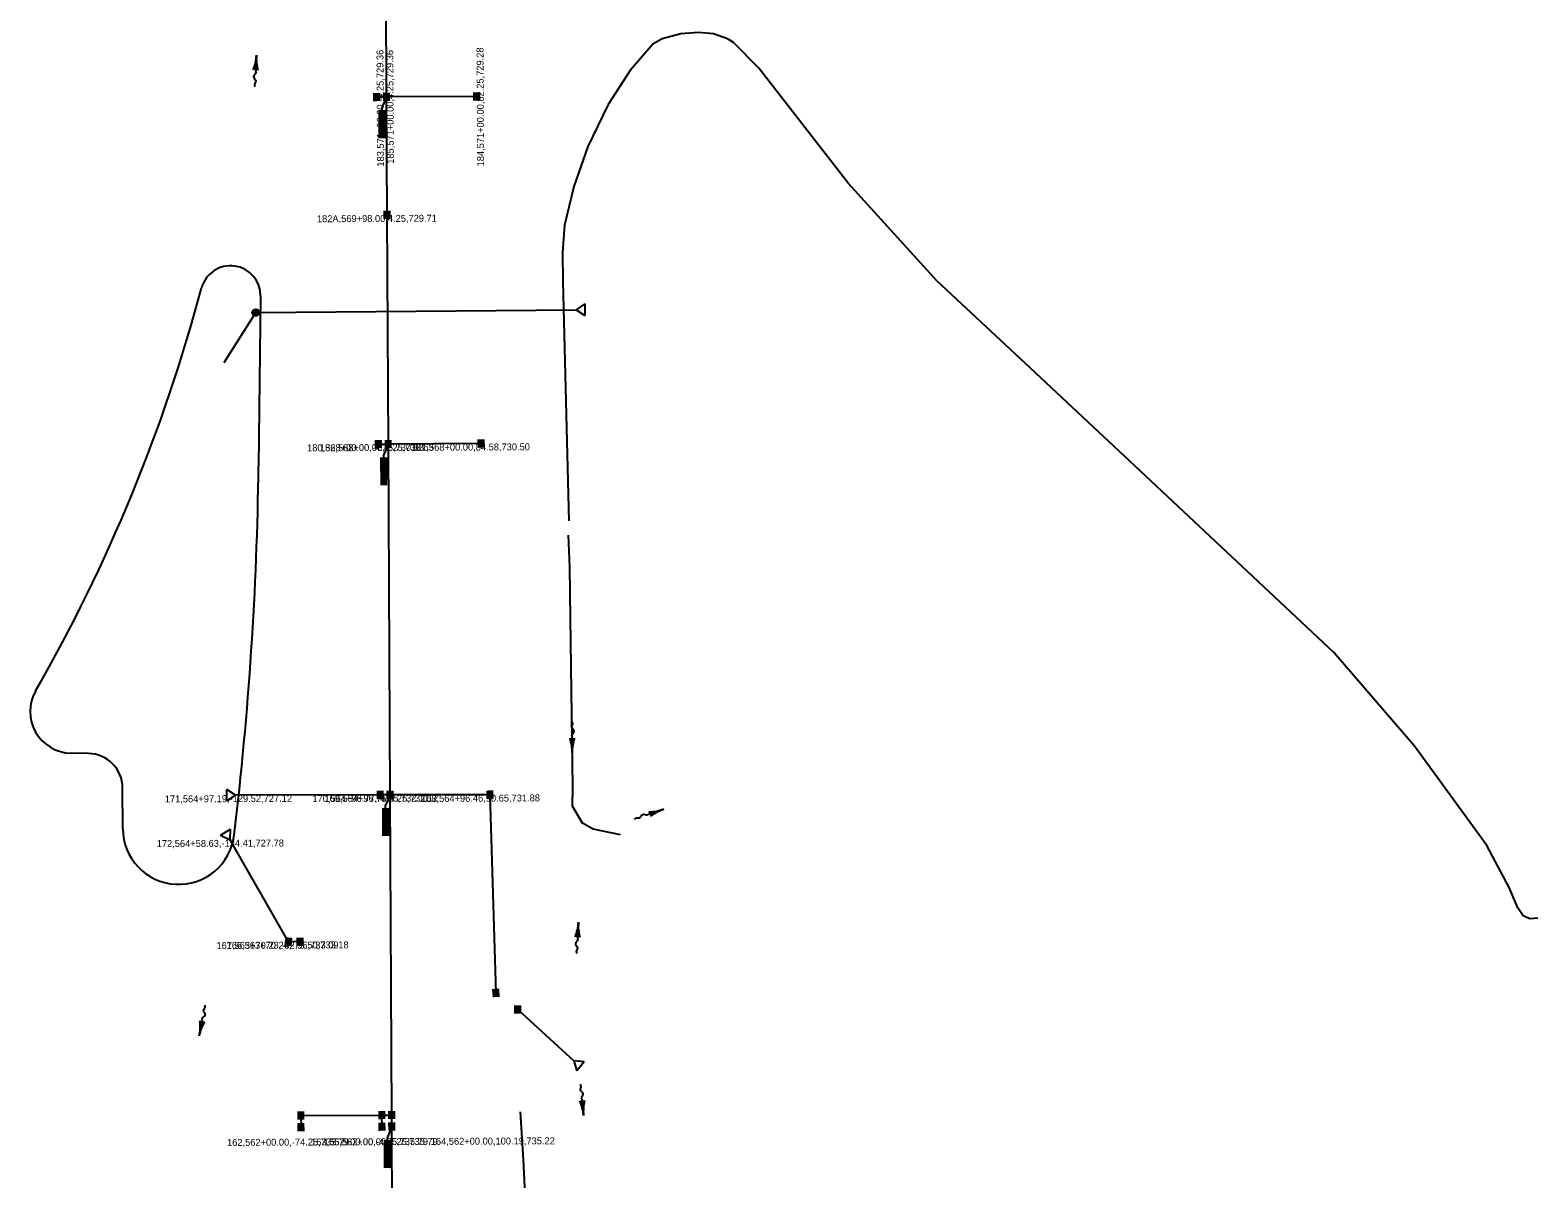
# Model space of a CAD drawing. Extents: x 593481 to 595602, y 151646 to 157396.
# Drawn here: x 594042 to 595346, y 155440 to 156433 of the extents above; entities that cross this region are included whole.
import ezdxf

# ---------------------------------------------------------------- set-up
doc = ezdxf.new("R2010")
doc.units = 0
for name, color, linetype in [('P_ALI_50_Equation', 7, 'Continuous'), ('P_DRN_Flow', 7, 'Continuous'), ('P_DRN_Inlet', 7, 'Continuous'), ('P_DRN_Pond', 7, 'Continuous'), ('P_DRN_SS', 7, 'Continuous'), ('P_DRN_SS_MH', 7, 'Continuous'), ('P_DRN_SS_UG', 7, 'Continuous')]:
    doc.layers.add(name, color=color, linetype=linetype)

msp = doc.modelspace()

# ---------------------------------------------------------------- linework, layer by layer
at = {"layer": 'P_DRN_Flow'}
for p, q in [((594238, 156411.3), (594237.2, 156397.2)), ((594510.9, 155808.1), (594511, 155822.3)), ((594590.1, 155759.5), (594576.7, 155755)), ((594516.3, 155661.9), (594515.5, 155647.8)), ((594188.6, 155563.7), (594191.3, 155577.6)), ((594520.8, 155494.8), (594519.5, 155508.9))]:
    msp.add_line(p, q, dxfattribs=at)
for points in [[(594239.3, 156398.4), (594237.5, 156401.7), (594235.3, 156398.6)], [(594509, 155820.9), (594511, 155817.7), (594513, 155820.9)], [(594578.6, 155753.5), (594581, 155756.5), (594577.3, 155757.3)], [(594517.6, 155649), (594515.7, 155652.3), (594513.6, 155649.2)], [(594189.1, 155576.7), (594190.4, 155573.2), (594193, 155575.9)], [(594517.6, 155507.4), (594519.9, 155504.4), (594521.6, 155507.8)]]:
    msp.add_lwpolyline(points, dxfattribs=at)
for centre, start, end in [((594196.1, 156413.6), 339.0322, 356.7946), ((594279.9, 156408.9), 176.7946, 194.5569), ((594469, 155808.4), 359.6117, 17.374), ((594552.9, 155807.9), 161.8494, 179.6117), ((594576.8, 155799.3), 270.74, 288.5023), ((594603.4, 155719.7), 108.5023, 126.2646), ((594474.4, 155664.2), 339.0322, 356.7946), ((594558.2, 155659.5), 176.7946, 194.5569), ((594147.4, 155571.7), 349.0067, 6.769), ((594229.8, 155555.7), 151.2443, 169.0067), ((594479, 155490.9), 5.4126, 23.1749), ((594562.6, 155498.8), 167.6503, 185.4126)]:
    msp.add_arc(centre, 42, start, end, dxfattribs=at)
for points in [[(594237.2, 156397.2), (594237.5, 156396.4), (594235.4, 156392.9), (594237.4, 156388.8), (594236.3, 156386), (594236.8, 156384.3)], [(594511, 155822.3), (594510.7, 155823.1), (594512.6, 155826.7), (594510.5, 155830.6), (594511.4, 155833.4), (594510.8, 155835.1)], [(594576.7, 155755), (594576, 155754.5), (594572, 155755.1), (594569, 155751.8), (594566, 155751.8), (594564.6, 155750.6)], [(594515.5, 155647.8), (594515.8, 155647), (594513.7, 155643.5), (594515.6, 155639.4), (594514.5, 155636.7), (594515.1, 155634.9)], [(594191.3, 155577.6), (594191.1, 155578.4), (594193.7, 155581.6), (594192.3, 155585.9), (594193.7, 155588.5), (594193.4, 155590.3)], [(594519.5, 155508.9), (594519.1, 155509.6), (594520.6, 155513.4), (594518.1, 155517.1), (594518.7, 155520), (594517.9, 155521.7)]]:
    msp.add_spline(points, degree=3, dxfattribs=at)
at = {"layer": 'P_DRN_Inlet'}
for p, q in [((594339.8, 156371.7), (594339.8, 156378.6)), ((594340.7, 156371.7), (594340.7, 156378.6)), ((594341.6, 156371.7), (594341.6, 156378.6)), ((594342.5, 156371.8), (594342.5, 156378.6)), ((594343.4, 156371.8), (594343.4, 156378.6)), ((594344.3, 156371.8), (594344.3, 156378.6)), ((594348.3, 156371.8), (594348.3, 156378.7)), ((594349.2, 156371.8), (594349.2, 156378.7)), ((594350.1, 156371.8), (594350.1, 156378.7)), ((594351, 156371.8), (594351, 156378.7)), ((594351.9, 156371.8), (594351.9, 156378.7)), ((594352.8, 156371.8), (594352.8, 156378.7)), ((594426.3, 156372.2), (594426.3, 156379.1)), ((594427.2, 156372.2), (594427.2, 156379.1)), ((594428.1, 156372.2), (594428.1, 156379.1)), ((594429, 156372.2), (594429, 156379.1)), ((594429.9, 156372.2), (594429.9, 156379.1)), ((594430.8, 156372.2), (594430.8, 156379.1)), ((594344.1, 156363.7), (594344.2, 156339.7)), ((594345, 156363.7), (594345.1, 156339.7)), ((594345.9, 156363.7), (594346, 156339.7)), ((594346.8, 156363.7), (594346.9, 156339.7)), ((594347.7, 156363.7), (594347.8, 156339.7)), ((594348.6, 156363.7), (594348.7, 156339.7)), ((594348.8, 156269.8), (594348.8, 156276.7)), ((594349.7, 156269.8), (594349.7, 156276.7)), ((594350.6, 156269.8), (594350.6, 156276.7)), ((594351.5, 156269.8), (594351.5, 156276.7)), ((594352.4, 156269.8), (594352.4, 156276.7)), ((594353.3, 156269.8), (594353.3, 156276.7)), ((594341.3, 156071.7), (594341.3, 156078.6)), ((594342.2, 156071.7), (594342.2, 156078.6)), ((594343.1, 156071.8), (594343.1, 156078.6)), ((594344, 156071.8), (594344, 156078.6)), ((594344.9, 156071.8), (594344.9, 156078.6)), ((594345.8, 156071.8), (594345.8, 156078.6)), ((594349.8, 156071.8), (594349.8, 156078.7)), ((594350.7, 156071.8), (594350.7, 156078.7)), ((594351.6, 156071.8), (594351.6, 156078.7)), ((594352.5, 156071.8), (594352.5, 156078.7)), ((594353.4, 156071.8), (594353.4, 156078.7)), ((594354.3, 156071.8), (594354.3, 156078.7)), ((594430.2, 156072.2), (594430.1, 156079)), ((594431.1, 156072.2), (594431, 156079)), ((594432, 156072.2), (594431.9, 156079.1)), ((594432.9, 156072.2), (594432.8, 156079.1)), ((594433.8, 156072.2), (594433.7, 156079.1)), ((594434.7, 156072.3), (594434.6, 156079.1)), ((594345.6, 156063.7), (594345.7, 156039.7)), ((594346.5, 156063.7), (594346.6, 156039.7)), ((594347.4, 156063.7), (594347.5, 156039.7)), ((594348.3, 156063.7), (594348.4, 156039.7)), ((594349.2, 156063.7), (594349.3, 156039.7)), ((594350.1, 156063.7), (594350.2, 156039.7)), ((594342.9, 155768.5), (594342.9, 155775.4)), ((594343.8, 155768.5), (594343.8, 155775.4)), ((594344.7, 155768.5), (594344.7, 155775.4)), ((594345.6, 155768.5), (594345.6, 155775.4)), ((594346.5, 155768.5), (594346.5, 155775.4)), ((594347.4, 155768.5), (594347.4, 155775.4)), ((594351.4, 155768.5), (594351.4, 155775.4)), ((594352.3, 155768.5), (594352.3, 155775.4)), ((594353.2, 155768.5), (594353.2, 155775.4)), ((594354.1, 155768.5), (594354.1, 155775.4)), ((594355, 155768.6), (594355, 155775.4)), ((594355.9, 155768.6), (594355.9, 155775.4)), ((594437.9, 155768.6), (594437.7, 155775.5)), ((594438.8, 155768.7), (594438.6, 155775.5)), ((594439.7, 155768.7), (594439.5, 155775.6)), ((594440.6, 155768.7), (594440.4, 155775.6)), ((594441.5, 155768.7), (594441.3, 155775.6)), ((594442.4, 155768.8), (594442.2, 155775.6)), ((594347.2, 155760.5), (594347.3, 155736.5)), ((594348.1, 155760.5), (594348.2, 155736.5)), ((594349, 155760.5), (594349.1, 155736.5)), ((594349.9, 155760.5), (594350, 155736.5)), ((594350.8, 155760.5), (594350.9, 155736.5)), ((594351.7, 155760.5), (594351.8, 155736.5)), ((594263.2, 155641.8), (594263.9, 155648.7)), ((594264.1, 155641.7), (594264.8, 155648.6)), ((594265, 155641.7), (594265.7, 155648.5)), ((594265.9, 155641.6), (594266.6, 155648.4)), ((594266.8, 155641.5), (594267.5, 155648.3)), ((594267.7, 155641.4), (594268.4, 155648.2)), ((594273.5, 155641.6), (594273.5, 155648.5)), ((594274.4, 155641.6), (594274.4, 155648.5)), ((594275.3, 155641.6), (594275.3, 155648.5)), ((594276.2, 155641.6), (594276.2, 155648.5)), ((594277.1, 155641.6), (594277.1, 155648.5)), ((594278, 155641.7), (594278, 155648.5)), ((594443.1, 155597.2), (594442.7, 155604.1)), ((594444, 155597.3), (594443.6, 155604.1)), ((594444.9, 155597.3), (594444.5, 155604.2)), ((594445.8, 155597.4), (594445.4, 155604.2)), ((594446.7, 155597.4), (594446.3, 155604.3)), ((594447.6, 155597.5), (594447.2, 155604.3)), ((594461.8, 155582.9), (594461.8, 155589.8)), ((594462.7, 155582.9), (594462.7, 155589.8)), ((594463.6, 155582.9), (594463.6, 155589.8)), ((594464.5, 155583), (594464.5, 155589.8)), ((594465.4, 155583), (594465.4, 155589.8)), ((594466.3, 155583), (594466.3, 155589.8)), ((594274.3, 155491.4), (594274.3, 155498.3)), ((594275.2, 155491.4), (594275.2, 155498.3)), ((594276.1, 155491.4), (594276.1, 155498.3)), ((594277, 155491.4), (594277, 155498.3)), ((594277.9, 155491.4), (594277.9, 155498.3)), ((594278.8, 155491.4), (594278.8, 155498.3)), ((594344.3, 155491.7), (594344.3, 155498.6)), ((594345.2, 155491.8), (594345.2, 155498.6)), ((594346.1, 155491.8), (594346.1, 155498.6)), ((594347, 155491.8), (594347, 155498.6)), ((594347.9, 155491.8), (594347.9, 155498.6)), ((594348.8, 155491.8), (594348.8, 155498.6)), ((594352.8, 155491.8), (594352.8, 155498.7)), ((594353.7, 155491.8), (594353.7, 155498.7)), ((594354.6, 155491.8), (594354.6, 155498.7)), ((594355.5, 155491.8), (594355.5, 155498.7)), ((594356.4, 155491.8), (594356.4, 155498.7)), ((594357.3, 155491.8), (594357.3, 155498.7)), ((594274.4, 155481.4), (594274.3, 155488.3)), ((594275.3, 155481.4), (594275.2, 155488.3)), ((594276.2, 155481.4), (594276.1, 155488.3)), ((594277.1, 155481.4), (594277, 155488.3)), ((594278, 155481.4), (594277.9, 155488.3)), ((594278.9, 155481.4), (594278.8, 155488.3)), ((594344.4, 155481.7), (594344.3, 155488.6)), ((594345.3, 155481.8), (594345.2, 155488.6)), ((594346.2, 155481.8), (594346.1, 155488.6)), ((594347.1, 155481.8), (594347, 155488.6)), ((594348, 155481.8), (594347.9, 155488.6)), ((594348.9, 155481.8), (594348.8, 155488.6)), ((594352.9, 155481.8), (594352.8, 155488.7)), ((594353.8, 155481.8), (594353.7, 155488.7)), ((594354.7, 155481.8), (594354.6, 155488.7)), ((594355.6, 155481.8), (594355.5, 155488.7)), ((594356.5, 155481.8), (594356.4, 155488.7)), ((594357.4, 155481.8), (594357.3, 155488.7)), ((594348.6, 155473.5), (594348.8, 155449.5)), ((594349.5, 155473.5), (594349.7, 155449.5)), ((594350.4, 155473.6), (594350.6, 155449.6)), ((594351.3, 155473.6), (594351.5, 155449.6)), ((594352.2, 155473.6), (594352.4, 155449.6)), ((594353.1, 155473.6), (594353.3, 155449.6))]:
    msp.add_line(p, q, dxfattribs=at)
for points in [[(594343, 156374.2), (594343, 156376.2), (594341, 156376.2), (594341, 156374.2)], [(594351.5, 156374.2), (594351.5, 156376.2), (594349.5, 156376.2), (594349.5, 156374.2)], [(594429.5, 156374.6), (594429.5, 156376.6), (594427.5, 156376.6), (594427.5, 156374.6)], [(594345.3, 156359), (594345.4, 156344.4), (594347.4, 156344.4), (594347.3, 156359)], [(594352.1, 156272.2), (594352, 156274.2), (594350, 156274.2), (594350.1, 156272.2)], [(594344.6, 156074.2), (594344.6, 156076.2), (594342.6, 156076.2), (594342.6, 156074.2)], [(594353.1, 156074.2), (594353.1, 156076.2), (594351.1, 156076.2), (594351.1, 156074.2)], [(594433.4, 156074.7), (594433.4, 156076.7), (594431.4, 156076.6), (594431.4, 156074.6)], [(594346.9, 156058.9), (594347, 156044.4), (594349, 156044.4), (594348.9, 156058.9)], [(594346.1, 155771), (594346.1, 155773), (594344.1, 155773), (594344.1, 155771)], [(594354.6, 155771), (594354.6, 155773), (594352.6, 155773), (594352.6, 155771)], [(594441, 155771.2), (594441, 155773.2), (594439, 155773.1), (594439.1, 155771.1)], [(594348.4, 155755.8), (594348.5, 155741.2), (594350.5, 155741.2), (594350.4, 155755.8)], [(594266.7, 155643.9), (594266.9, 155645.9), (594264.9, 155646.1), (594264.7, 155644.1)], [(594276.8, 155644.1), (594276.8, 155646.1), (594274.8, 155646.1), (594274.8, 155644.1)], [(594446.2, 155599.8), (594446.1, 155601.8), (594444.1, 155601.7), (594444.2, 155599.7)], [(594465.1, 155585.4), (594465, 155587.4), (594463, 155587.4), (594463.1, 155585.4)], [(594347.5, 155494.2), (594347.5, 155496.2), (594345.5, 155496.2), (594345.5, 155494.2)], [(594356, 155494.2), (594356, 155496.2), (594354, 155496.2), (594354, 155494.2)], [(594277.5, 155493.8), (594277.5, 155495.8), (594275.5, 155495.8), (594275.5, 155493.8)], [(594277.6, 155483.8), (594277.6, 155485.8), (594275.6, 155485.8), (594275.6, 155483.8)], [(594347.6, 155484.2), (594347.6, 155486.2), (594345.6, 155486.2), (594345.6, 155484.2)], [(594356.1, 155484.3), (594356.1, 155486.3), (594354.1, 155486.2), (594354.1, 155484.2)], [(594349.9, 155468.8), (594350, 155454.3), (594352, 155454.3), (594351.9, 155468.8)]]:
    msp.add_lwpolyline(points, close=True, dxfattribs=at)
at = {"layer": 'P_DRN_Pond'}
for p, q in [((594241.6, 156203), (594239.8, 156056.5)), ((594092.9, 155807.7), (594077.7, 155808)), ((594122.5, 155742.7), (594122.3, 155777.9))]:
    msp.add_line(p, q, dxfattribs=at)
for centre, radius, start, end in [((594215.6, 156203.3), 26, 359.2941, 165.091), ((592792.2, 156582.3), 1447, 330.142, 345.091), ((591269.1, 156093.1), 2971, 353.1195, 359.2941), ((594078.4, 155844), 36, 150.142, 268.9825), ((594092.3, 155777.7), 30, 0.2941, 88.9825), ((594170.8, 155742.9), 48.3, 180.2941, 353.1195)]:
    msp.add_arc(centre, radius, start, end, dxfattribs=at)
at = {"layer": 'P_DRN_SS'}
for p, q in [((594521.9, 156196.4), (594514.4, 156191.3)), ((594514.4, 156191.3), (594521.9, 156186.4)), ((594521.9, 156196.4), (594521.9, 156186.4)), ((594219.8, 155771.7), (594212.3, 155776.7)), ((594212.4, 155766.7), (594212.3, 155776.7)), ((594212.4, 155766.7), (594219.8, 155771.7)), ((594207, 155737.1), (594215.7, 155742.2)), ((594207, 155737.1), (594215.2, 155733.2)), ((594215.2, 155733.2), (594215.7, 155742.2)), ((594521.3, 155541.2), (594512.3, 155542.2)), ((594512.3, 155542.2), (594514.9, 155533.5)), ((594521.3, 155541.2), (594514.9, 155533.5))]:
    msp.add_line(p, q, dxfattribs=at)
at = {"layer": 'P_DRN_SS_MH'}
for radius in [2.98, 2.4, 1.8, 1.2, 0.6]:
    msp.add_circle((594237.4, 156188.9), radius, dxfattribs=at)
at = {"layer": 'P_DRN_SS_UG'}
for p, q in [((594350.5, 156375.2), (594349.1, 156655.2)), ((594342, 156375.2), (594350.5, 156375.2)), ((594428.5, 156375.6), (594350.5, 156375.2)), ((594351, 156273.2), (594350.5, 156375.2)), ((594352.1, 156075.2), (594351, 156273.2)), ((594210.2, 156145.7), (594237.4, 156188.9)), ((594237.4, 156188.9), (594514.4, 156191.3)), ((594343.6, 156075.2), (594352.1, 156075.2)), ((594432.4, 156075.6), (594352.1, 156075.2)), ((594353.6, 155772), (594352.1, 156075.2)), ((594345.1, 155772), (594219.8, 155771.7)), ((594353.6, 155772), (594345.1, 155772)), ((594440, 155772.1), (594353.6, 155772)), ((594355, 155495.2), (594353.6, 155772)), ((594445.2, 155600.8), (594440, 155772.1)), ((594265.8, 155645), (594215.2, 155733.2)), ((594275.8, 155645.1), (594265.8, 155645)), ((594464.1, 155586.4), (594512.3, 155542.2)), ((594276.5, 155494.8), (594346.5, 155495.2)), ((594276.5, 155494.8), (594276.6, 155484.8)), ((594346.5, 155495.2), (594355, 155495.2)), ((594346.6, 155485.2), (594346.5, 155495.2)), ((594355.1, 155485.3), (594355, 155495.2)), ((594355.9, 155330.2), (594355.1, 155485.3))]:
    msp.add_line(p, q, dxfattribs=at)
for points in [[(595345.8, 155665.5), (595338.9, 155664.9), (595333.1, 155667.3), (595328.4, 155674.3), (595321, 155691.9), (595301.8, 155728.2), (595239.2, 155814.2), (595169.4, 155895), (594997.8, 156056.2), (594907.2, 156140.8), (594826.3, 156216.4), (594749.6, 156300.6), (594672.2, 156400.2), (594650.5, 156422.2), (594645.2, 156425.4), (594633, 156429.8), (594620.3, 156430.9), (594605, 156429.9), (594588.7, 156425.4), (594580.7, 156420.9), (594561, 156398.2), (594542.2, 156368.7), (594524.6, 156332.4), (594512.5, 156297.9), (594504.2, 156264.4), (594502.7, 156240.9), (594503, 156215.3), (594508, 156008.7)], [(594350.5, 156375.2), (594346.3, 156365.7), (594346.3, 156363.7)], [(594352.1, 156075.2), (594347.9, 156065.7), (594347.9, 156063.7)], [(594552.8, 155737.4), (594529.2, 155742.3), (594520, 155747.6), (594511.1, 155762.2), (594511.5, 155778.5), (594509.6, 155924.8), (594508.9, 155968.8), (594507.7, 155996.4)], [(594353.6, 155772), (594349.4, 155762.5), (594349.4, 155760.5)], [(594571.9, 155365.7), (594565.1, 155352.4), (594559.6, 155349.7), (594555.9, 155350.1), (594550.3, 155352), (594541.4, 155353.2), (594531.1, 155354.6), (594526.6, 155355.9), (594522.9, 155359.6), (594515.3, 155368.1), (594504.6, 155372.8), (594491.2, 155377.9), (594483.8, 155384), (594477.1, 155395.2), (594470.9, 155414.9), (594468.9, 155456.7), (594466.2, 155498)], [(594355.1, 155485.3), (594350.9, 155475.6), (594350.9, 155473.6)]]:
    msp.add_lwpolyline(points, dxfattribs=at)

# ---------------------------------------------------------------- texts
at = {"layer": 'P_ALI_50_Equation'}
for s, rotation, p in [('183,571+00.00,-4.25,729.36', 90.2941, (594348.3, 156315)), ('185,571+00.00,4.25,729.36', 90.2941, (594356.8, 156317.5)), ('184,571+00.00,82.25,729.28', 90.2941, (594434.8, 156315.2)), ('182A,569+98.00,4.25,729.71', 0.2941, (594290.3, 156266.9)), ('180,568+00.00,-4.25,730.63', 0.2941, (594281.8, 156068.9)), ('182,568+00.00,4.25,730.63', 0.2941, (594292.9, 156068.9)), ('181,568+00.00,84.58,730.50', 0.2941, (594371.6, 156069.3)), ('171,564+97.19,-129.52,727.12', 0.2941, (594158.8, 155765.4)), ('170,564+96.77,-4.25,732.11', 0.2941, (594286.4, 155765.7)), ('169,564+96.75,4.25,732.12', 0.2941, (594296.8, 155765.7)), ('168,564+96.46,90.65,731.88', 0.2941, (594380.3, 155765.8)), ('172,564+58.63,-134.41,727.78', 0.2941, (594151.8, 155726.8)), ('167,563+70.23,-82.96,733.09', 0.2941, (594203.5, 155638.7)), ('166,563+70.24,-75.50,733.18', 0.2941, (594212.2, 155638.8)), ('162,562+00.00,-74.25,735.79', 0.2941, (594212.6, 155468.5)), ('163,562+00.00,-4.25,735.79', 0.2941, (594285.3, 155468.9)), ('165,562+00.00,4.25,735.79', 0.2941, (594296.3, 155468.9)), ('164,562+00.00,100.19,735.22', 0.2941, (594388.7, 155469.4))]:
    msp.add_text(s, height=6, rotation=rotation, dxfattribs=at).set_placement(p)

doc.saveas('drawing.dxf')
